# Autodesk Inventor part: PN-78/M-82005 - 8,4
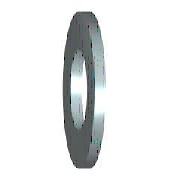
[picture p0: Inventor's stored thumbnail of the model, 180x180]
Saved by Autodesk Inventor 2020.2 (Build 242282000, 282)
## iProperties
Manager: www.cadconsulting.pl
Company: Fabian Stasiak CAD Consulting
Created: 2006-02
Part Number: PN-78/M-82005 - 8,4
Material: Stal, miękka
Description: Podkładki okrągłe, szereg nieobrobiony
Document SubType Name: Modeling
Standard: PN-78/M-82005
Designer: F.Stasiak
Standards Organization: PN
Language: pl-PL
Size Designation: 8,4
Categories: <MemberInstance><Categories><Category DisplayName="Mocowania" InternalName="e4da775c-781d-43d5-af7c-5136215cf5a6" Mnemonic="FSTN"><Category DisplayName="Podkład
Density: 7.86 g/cm^3
Mass: 2.15757 g
Surface Area: 4.70799 cm^2
Volume: 0.2745 cm^3
Appearance: Metal-Stal
Author: F.Stasiak
Subject: Zbiór ćwiczeń. Autodesk Inventor 2020. Kurs podstawowy
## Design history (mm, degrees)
sketch "Szkic"
  geometry: C1 r 8.5 at (0, 0); C2 r 4.2 at (0, 0); 1 further point
  constraints: 2 centre point, 2 coincident
  dimensions: "d0" = 8.4 diameter of C2 (= SD1); "d1" = 17 diameter of C1 (= SD2)
extrude "Bryła" new body sketch "Szkic" distance "d2" = 1.6 (= SD); taper "d3" = 0 deg
workaxis "Work Axis1"
workplane "Work Plane1"
node "Bryła1"
node "Korpusy bryłowe"
node "Korpusy powierzchniowe"
other parameters: "SD1" = 8.4 [user parameter; used in 1 equation term], "SD2" = 17 [user parameter; used in 1 equation term], "SD" = 1.6 [user parameter; used in 1 equation term], "d4" = 0, "d5" = 0, "d6" = 0, "d7" = 0, "NND" = 8 [user parameter]
